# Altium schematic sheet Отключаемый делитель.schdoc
size 126 x 112 mm
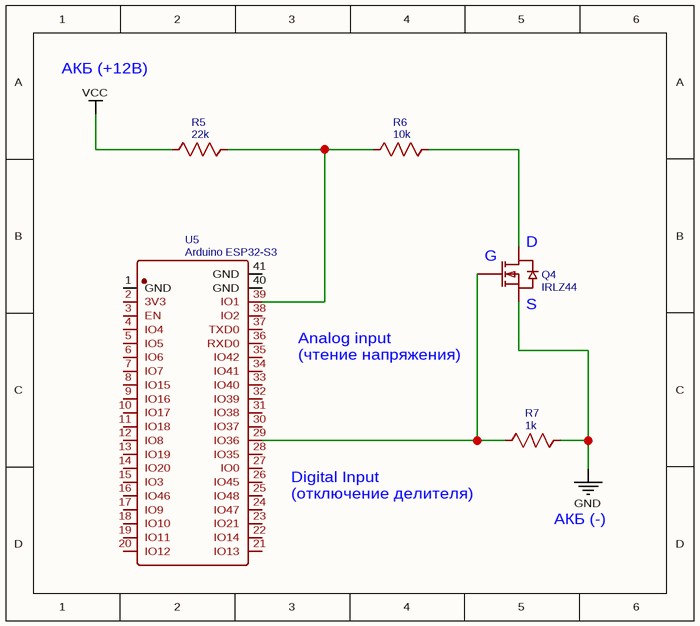
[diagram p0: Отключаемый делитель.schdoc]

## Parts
Q4  IRLZ44  [TO-220-3_L10.0-W4.5-P2.54-T]
R5  22k  [R0603]
R6  10k  [R0603]
R7  1k  [R0603]
U5  Arduino ESP32-S3  [WIRELM-SMD_ESP32-S3-WROOM-1U]

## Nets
GND: Q4.3(S) R7.2
VCC: R5.1
NetQ4_1: Q4.1(G) R7.1 U5.29(IO36)
NetQ4_2: Q4.2(D) R6.2
NetR5_2: R5.2 R6.1 U5.39(IO1)

Not connected (* = marked no-connect by the designer): U5 1(GND) 2(3V3) 3(EN) 4(IO4) 5(IO5) 6(IO6) 7(IO7) 8(IO15) 9(IO16) 10(IO17) 11(IO18) 12(IO8) 13(IO19) 14(IO20) 15(IO3) 16(IO46) 17(IO9) 18(IO10) 19(IO11) 20(IO12) 21(IO13) 22(IO14) 23(IO21) 24(IO47) 25(IO48) 26(IO45) 27(IO0) 28(IO35) 30(IO37) 31(IO38) 32(IO39) 33(IO40) 34(IO41) 35(IO42) 36(RXD0) 37(TXD0) 38(IO2) 40(GND) 41(GND)

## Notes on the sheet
- АКБ (+12В)
- (near Q4) G
- (near Q4) D
- Analog input
  (чтение напряжения)
- (near Q4) S
- (near U5) Digital Input
  (отключение делителя)
- АКБ (-)

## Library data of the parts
Q4 = IRLZ44: Manufacturer: Infineon(英飞凌); Manufacturer Part: IRLZ44NPBF
R5 = 22k: nameAlias: Value(Ω); Contributor: LCEDA_Lib
R6 = 10k: nameAlias: Value(Ω); Contributor: LCEDA_Lib
R7 = 1k: nameAlias: Value(Ω); Contributor: LCEDA_Lib
U5 = Arduino ESP32-S3: Manufacturer: null; Manufacturer Part: ESP32-S3-WROOM-1U; Contributor: lcsc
